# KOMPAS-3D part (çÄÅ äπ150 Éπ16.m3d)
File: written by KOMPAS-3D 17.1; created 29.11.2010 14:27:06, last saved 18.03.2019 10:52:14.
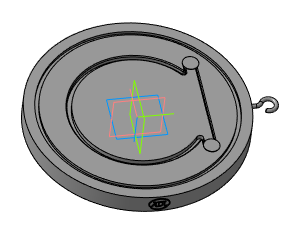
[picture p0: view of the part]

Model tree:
1. Плоскость XY
2. Плоскость ZX
3. Плоскость ZY
4. Ось X
5. Ось Y
6. Ось Z
7. Начало координат
8. Операция без истории:2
